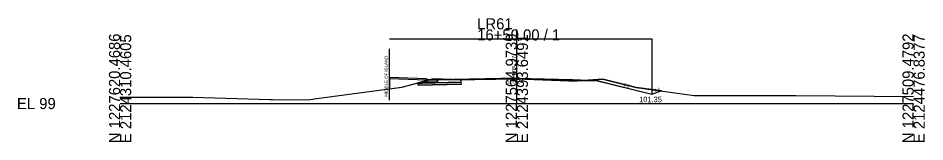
# Model space of a CAD drawing. Extents: x 2121193 to 2127979, y 1225108 to 1234639.
# Drawn here: x 2127750.9 to 2127979.4, y 1231607.5 to 1231638.8 of the extents above; entities that cross this region are included whole.
import ezdxf

# ---------------------------------------------------------------- set-up
doc = ezdxf.new("R2010")
doc.units = 0
for name, color, linetype in [('TS_CURB_GUTTER', 7, 'Continuous'), ('XS_CELL', 7, 'Continuous'), ('XS_M_DITCH', 7, 'Continuous'), ('XS_M_SHAPES_EARTHWORK', 7, 'Continuous'), ('XS_P_DR_CONCRETE', 7, 'Continuous'), ('XS_P_FINISHED_GRADE', 7, 'Continuous'), ('XS_P_FINISHED_GRADE_ELEV_TX', 7, 'Continuous'), ('XS_P_SUBGRADE_GRANULAR', 7, 'Continuous'), ('XS_P_SUBGRADE_LEVELING', 7, 'Continuous'), ('XS_P_SUBGRADE_PAVEMENT', 7, 'Continuous'), ('XS_P_TX_DCH', 7, 'Continuous'), ('XS_P_TX_FS_BS', 7, 'Continuous'), ('XS_X_GROUND', 7, 'Continuous'), ('XS_X_GROUND_TX', 7, 'Continuous')]:
    doc.layers.add(name, color=color, linetype=linetype)

msp = doc.modelspace()

# ---------------------------------------------------------------- linework, layer by layer
at = {"layer": 'TS_CURB_GUTTER'}
msp.add_lwpolyline([(2127856.61, 1231623.18), (2127856.62, 1231622.68), (2127853.87, 1231622.62), (2127853.84, 1231623.44), (2127853.84, 1231623.45), (2127853.84, 1231623.45), (2127853.85, 1231623.45), (2127853.85, 1231623.45), (2127854.55, 1231623.24), (2127854.58, 1231623.22), (2127854.6, 1231623.2), (2127854.61, 1231623.16), (2127854.61, 1231623.14), (2127856.61, 1231623.18)], dxfattribs=at)
at = {"layer": 'XS_CELL'}
for p, q in [((2127876.61, 1231617.21), (2127876.61, 1231635.95)), ((2127776.61, 1231617.21), (2127876.61, 1231617.21)), ((2127876.61, 1231617.21), (2127976.61, 1231617.21))]:
    msp.add_line(p, q, dxfattribs=at)
at = {"layer": 'XS_M_DITCH'}
for p, q in [((2127844.53, 1231633.58), (2127910.61, 1231633.58)), ((2127910.61, 1231633.58), (2127910.61, 1231619.56)), ((2127851.75, 1231622.39), (2127851.75, 1231622.45))]:
    msp.add_line(p, q, dxfattribs=at)
at = {"layer": 'XS_M_SHAPES_EARTHWORK'}
for p, q in [((2127844.53, 1231623.81), (2127844.53, 1231620.96)), ((2127853.85, 1231623.11), (2127844.53, 1231623.48)), ((2127844.53, 1231623.48), (2127844.53, 1231620.96)), ((2127847.66, 1231621.38), (2127853.86, 1231623.01)), ((2127853.86, 1231623.01), (2127851.75, 1231622.45)), ((2127851.75, 1231622.45), (2127851.75, 1231622.39)), ((2127852.75, 1231622.39), (2127851.75, 1231622.39)), ((2127851.75, 1231622.39), (2127851.75, 1231621.87)), ((2127851.75, 1231622.39), (2127852.75, 1231622.39)), ((2127851.75, 1231621.87), (2127862.62, 1231622.09)), ((2127852.87, 1231622.6), (2127852.75, 1231622.39)), ((2127852.75, 1231622.39), (2127852.87, 1231622.6)), ((2127862.61, 1231622.59), (2127852.75, 1231622.39)), ((2127852.75, 1231622.39), (2127862.61, 1231622.59)), ((2127853.87, 1231622.62), (2127852.87, 1231622.6)), ((2127852.87, 1231622.6), (2127853.87, 1231622.62)), ((2127853.86, 1231623.01), (2127853.85, 1231623.11)), ((2127854.6, 1231623.2), (2127853.86, 1231623.01)), ((2127853.87, 1231622.62), (2127853.86, 1231623.01)), ((2127853.86, 1231623.01), (2127853.87, 1231622.62)), ((2127855.56, 1231623.46), (2127854.6, 1231623.2)), ((2127860.28, 1231623.25), (2127855.56, 1231623.46)), ((2127860.28, 1231623.25), (2127856.61, 1231623.18)), ((2127856.61, 1231623.18), (2127860.28, 1231623.25)), ((2127860.34, 1231623.25), (2127860.28, 1231623.25)), ((2127862.23, 1231623.16), (2127860.34, 1231623.25)), ((2127862.61, 1231623.16), (2127862.23, 1231623.16)), ((2127862.61, 1231622.59), (2127862.61, 1231623.16)), ((2127862.62, 1231622.09), (2127862.61, 1231622.59)), ((2127890.68, 1231623.17), (2127890.68, 1231622.93)), ((2127893.43, 1231623.06), (2127890.68, 1231623.17)), ((2127890.68, 1231622.93), (2127891.18, 1231622.95)), ((2127891.18, 1231622.95), (2127891.8, 1231622.97)), ((2127891.8, 1231622.97), (2127893.43, 1231623.06)), ((2127894.71, 1231623.14), (2127893.43, 1231623.06)), ((2127893.43, 1231623.06), (2127897.2, 1231622.91)), ((2127898.27, 1231623.34), (2127894.71, 1231623.14)), ((2127896.61, 1231623.06), (2127894.71, 1231623.14)), ((2127894.71, 1231623.14), (2127896.61, 1231623.06)), ((2127897.2, 1231622.91), (2127896.61, 1231623.06)), ((2127896.61, 1231623.06), (2127897.2, 1231622.91)), ((2127897.2, 1231622.91), (2127910.61, 1231619.56)), ((2127906.67, 1231621.27), (2127898.27, 1231623.34)), ((2127844.53, 1231620.96), (2127847.66, 1231621.38)), ((2127913.09, 1231620.38), (2127906.67, 1231621.27)), ((2127910.61, 1231619.56), (2127913.09, 1231620.38))]:
    msp.add_line(p, q, dxfattribs=at)
for points in [[(2127853.87, 1231622.62), (2127856.62, 1231622.68), (2127856.61, 1231623.18), (2127854.61, 1231623.14), (2127854.61, 1231623.16), (2127854.6, 1231623.2), (2127854.6, 1231623.2)], [(2127856.61, 1231623.18), (2127856.62, 1231622.68), (2127853.87, 1231622.62)], [(2127854.6, 1231623.2), (2127854.6, 1231623.2), (2127854.61, 1231623.16)], [(2127854.61, 1231623.16), (2127854.61, 1231623.14), (2127856.61, 1231623.18)]]:
    msp.add_lwpolyline(points, dxfattribs=at)
at = {"layer": 'XS_P_DR_CONCRETE'}
msp.add_line((2127853.85, 1231623.11), (2127844.53, 1231623.48), dxfattribs=at)
at = {"layer": 'XS_P_FINISHED_GRADE'}
for p, q in [((2127853.84, 1231623.44), (2127844.53, 1231623.81)), ((2127876.61, 1231623.58), (2127856.61, 1231623.18)), ((2127876.61, 1231623.58), (2127890.61, 1231623.3)), ((2127890.61, 1231623.3), (2127896.61, 1231623.06)), ((2127896.61, 1231623.06), (2127910.61, 1231619.56)), ((2127910.61, 1231619.56), (2127913.09, 1231620.38))]:
    msp.add_line(p, q, dxfattribs=at)
at = {"layer": 'XS_P_SUBGRADE_GRANULAR'}
for p, q in [((2127851.75, 1231621.87), (2127851.75, 1231622.45)), ((2127851.75, 1231622.39), (2127852.75, 1231622.39)), ((2127862.62, 1231622.09), (2127851.75, 1231621.87)), ((2127862.62, 1231622.09), (2127862.61, 1231622.59)), ((2127890.68, 1231623.17), (2127897.2, 1231622.91))]:
    msp.add_line(p, q, dxfattribs=at)
at = {"layer": 'XS_P_SUBGRADE_LEVELING'}
for p, q in [((2127876.61, 1231623.45), (2127862.61, 1231623.16)), ((2127889.69, 1231622.96), (2127876.61, 1231623.45)), ((2127890.62, 1231622.93), (2127889.69, 1231622.96)), ((2127890.68, 1231622.93), (2127890.62, 1231622.93))]:
    msp.add_line(p, q, dxfattribs=at)
at = {"layer": 'XS_P_SUBGRADE_PAVEMENT'}
for p, q in [((2127852.87, 1231622.6), (2127852.75, 1231622.39)), ((2127862.61, 1231622.59), (2127852.75, 1231622.39)), ((2127853.87, 1231622.62), (2127852.87, 1231622.6)), ((2127876.61, 1231623.45), (2127862.61, 1231623.17)), ((2127862.61, 1231622.59), (2127862.61, 1231623.17)), ((2127876.61, 1231623.45), (2127890.68, 1231623.17)), ((2127890.61, 1231623.3), (2127890.68, 1231623.17))]:
    msp.add_line(p, q, dxfattribs=at)
at = {"layer": 'XS_P_TX_FS_BS'}
msp.add_line((2127844.53, 1231618.07), (2127844.53, 1231631.04), dxfattribs=at)
at = {"layer": 'XS_X_GROUND'}
for p, q in [((2127847.66, 1231621.38), (2127855.56, 1231623.46)), ((2127855.56, 1231623.46), (2127860.34, 1231623.25)), ((2127860.34, 1231623.25), (2127862.23, 1231623.16)), ((2127862.23, 1231623.16), (2127866.06, 1231623.24)), ((2127866.06, 1231623.24), (2127876.61, 1231623.45)), ((2127876.61, 1231623.45), (2127889.69, 1231622.96)), ((2127889.69, 1231622.96), (2127890.62, 1231622.93)), ((2127890.62, 1231622.93), (2127891.18, 1231622.95)), ((2127891.18, 1231622.95), (2127891.8, 1231622.97)), ((2127891.8, 1231622.97), (2127898.27, 1231623.34)), ((2127898.27, 1231623.34), (2127906.67, 1231621.27)), ((2127825.49, 1231618.4), (2127847.66, 1231621.38)), ((2127906.67, 1231621.27), (2127921.33, 1231619.24)), ((2127776.58, 1231618.86), (2127779.8, 1231618.85)), ((2127779.8, 1231618.85), (2127780.81, 1231618.8)), ((2127780.81, 1231618.8), (2127794.96, 1231618.82)), ((2127794.96, 1231618.82), (2127814.36, 1231618.24)), ((2127814.36, 1231618.24), (2127815, 1231618.23)), ((2127815, 1231618.23), (2127824.21, 1231618.12)), ((2127824.21, 1231618.12), (2127825.49, 1231618.4)), ((2127921.33, 1231619.24), (2127946.93, 1231619.27)), ((2127946.93, 1231619.27), (2127976.58, 1231619))]:
    msp.add_line(p, q, dxfattribs=at)

# ---------------------------------------------------------------- texts
at = {"layer": 'XS_CELL'}
for s, p in [('LR61', (2127866.61, 1231635.95)), ('16+50.00 / 1', (2127866.61, 1231633.15)), ('EL 99', (2127750.61, 1231615.81))]:
    msp.add_text(s, height=2.8, dxfattribs=at).set_placement(p)
for s, p in [('N 1227620.4686', (2127776.61, 1231607.21)), ('E 2124310.4605', (2127779.41, 1231607.21)), ('N 1227564.9739', (2127876.61, 1231607.21)), ('E 2124393.6491', (2127879.41, 1231607.21)), ('N 1227509.4792', (2127976.61, 1231607.21)), ('E 2124476.8377', (2127979.41, 1231607.21))]:
    msp.add_text(s, height=2.8, rotation=90, dxfattribs=at).set_placement(p)
at = {"layer": 'XS_P_FINISHED_GRADE_ELEV_TX'}
msp.add_text(' 105.37', height=1.25, rotation=90, dxfattribs=at).set_placement((2127876.61, 1231623.58))
at = {"layer": 'XS_P_TX_DCH'}
msp.add_text('101.35', height=1.4, dxfattribs=at).set_placement((2127907.44, 1231617.55))
at = {"layer": 'XS_P_TX_FS_BS'}
for s, rotation, p in [('MIDDLE OF ISLAND', 90, (2127844.09, 1231618.96)), ('4:1', 345.9638, (2127903.38, 1231621.62)), ('3:1', 18.4349, (2127911.41, 1231620.05))]:
    msp.add_text(s, height=0.8, rotation=rotation, dxfattribs=at).set_placement(p)
at = {"layer": 'XS_X_GROUND_TX'}
msp.add_text('105.24', height=1, dxfattribs=at).set_placement((2127874.02, 1231622.29))

doc.saveas('drawing.dxf')
